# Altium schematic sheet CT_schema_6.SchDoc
size 266 x 267 mm
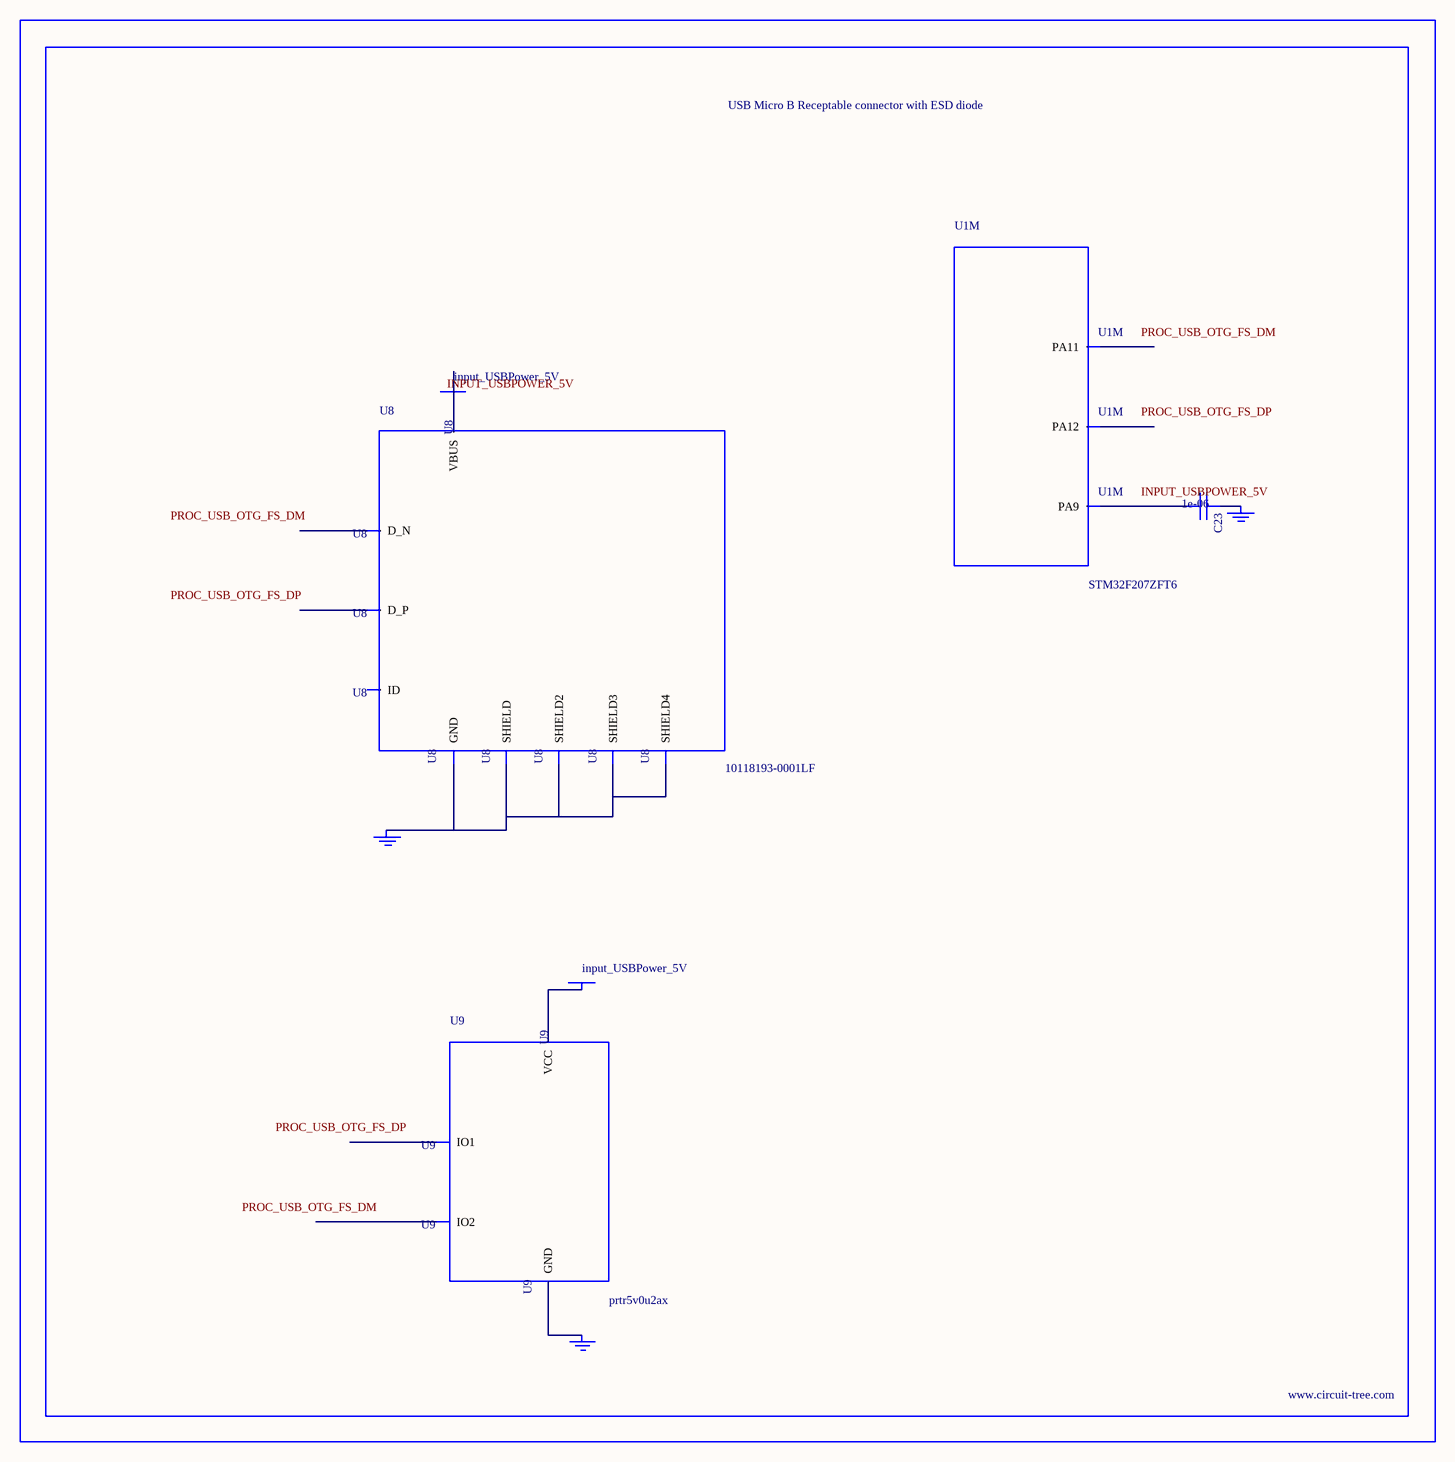
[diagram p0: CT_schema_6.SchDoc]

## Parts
BORDER5  (no value)
C23  1e-06  [C0603]
GND_INSTANCE_5_0  (no value)
GND_INSTANCE_5_1  (no value)
GND_INSTANCE_5_2  (no value)
POWER_INSTANCE_5_0  input_USBPower_5V
POWER_INSTANCE_5_1  input_USBPower_5V
U1  STM32F207ZFT6  [LQFP144]  (part M of 13)
U8  10118193-0001LF  [FCI_10118193-0001LF]
U9  prtr5v0u2ax  [SOT143B]

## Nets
NetC23_1: C23.1 GND_INSTANCE_5_1.0(GND)
NetC23_2: C23.2 U1.101(PA9)
NetGND_INSTANCE_5_0_0: GND_INSTANCE_5_0.0(GND) U8.5(GND) U8.6(SHIELD) U8.7(SHIELD2) U8.8(SHIELD3) U8.9(SHIELD4)
NetGND_INSTANCE_5_2_0: GND_INSTANCE_5_2.0(GND) U9.1(GND)
NetPOWER_INSTANCE_5_0_0: POWER_INSTANCE_5_0.0(PWR) U8.1(VBUS)
NetPOWER_INSTANCE_5_1_0: POWER_INSTANCE_5_1.0(PWR) U9.4(VCC)

Not connected (* = marked no-connect by the designer): U1 103(PA11) 104(PA12); U8 2(D_N) 3(D_P) 4(ID); U9 2(IO1) 3(IO2)

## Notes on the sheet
- Labels drawn without touching a wire or pin: INPUT_USBPOWER_5V, PROC_USB_OTG_FS_DM, PROC_USB_OTG_FS_DP

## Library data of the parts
BORDER5 = BORDER_PAGE5
C23 = C0603C105K3RACTU
GND_INSTANCE_5_0-GND_INSTANCE_5_2 = GND
POWER_INSTANCE_5_0 POWER_INSTANCE_5_1 = PWR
